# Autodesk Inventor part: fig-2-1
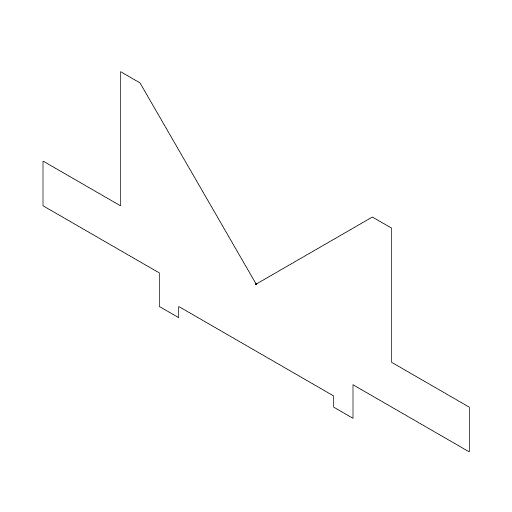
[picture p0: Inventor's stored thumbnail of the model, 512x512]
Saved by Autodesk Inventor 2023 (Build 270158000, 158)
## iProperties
Created: 2011-06
Part Number: fig-2-1
Material: Generic
Document SubType Name: Modeling
Designer: CadCim
Density: 1 g/cm^3
Appearance: Default
Author: CadCim
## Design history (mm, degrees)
sketch "Sketch1"
  geometry: L1 (2, -1.75)-(2.5, -1.75); L2 (-2.5, -1.75)-(-2, -1.75); L3 (-2, -1.75)-(-2, -2); L4 (-2.5, -2.5)-(-2.5, -1.75); L5 (-3, -6.5)-(-3.5, -6.5); L6 (-3.5, -6.5)-(-3.5, -3.5); L7 (-5.5, -2.5)-(-2.5, -2.5); L8 (-5.5, -3.5)-(-5.5, -2.5); L9 (-3.5, -3.5)-(-5.5, -3.5); L10 (0, -3.5)-(-3, -6.5); L11 (-2, -2)-(2, -2); L12 (3, -6.5)-(0, -3.5); L13 (2, -2)-(2, -1.75); L14 (2.5, -1.75)-(2.5, -2.5); L15 (3.5, -6.5)-(3, -6.5); L16 (3.5, -3.5)-(3.5, -6.5); L17 (5.5, -3.5)-(3.5, -3.5); L18 (2.5, -2.5)-(5.5, -2.5); L19 (5.5, -2.5)-(5.5, -3.5); 1 further point
  constraints: 38 end point
